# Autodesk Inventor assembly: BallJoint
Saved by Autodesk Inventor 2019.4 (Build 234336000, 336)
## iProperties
Created: 2020-04
Part Number: BallJoint
Document SubType Name: Assembly
Designer: Administrator
Title: BallJoint v14
Author: Administrator
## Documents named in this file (3)
- c:\worker\convert-fusion-r03\tmp\job-1\48\output\files\ccae6ef3-9f0e-42ff-b199-3a2c6474057a\BallJoint v14_6.iam
- c:\worker\convert-fusion-r03\tmp\job-1\48\output\files\ccae6ef3-9f0e-42ff-b199-3a2c6474057a\Component1_1.ipt
- c:\worker\convert-fusion-r03\tmp\job-1\48\output\files\ccae6ef3-9f0e-42ff-b199-3a2c6474057a\Component2_1.ipt
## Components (2 placed, 2 different names)
1. Component1:1
2. Component2:1
